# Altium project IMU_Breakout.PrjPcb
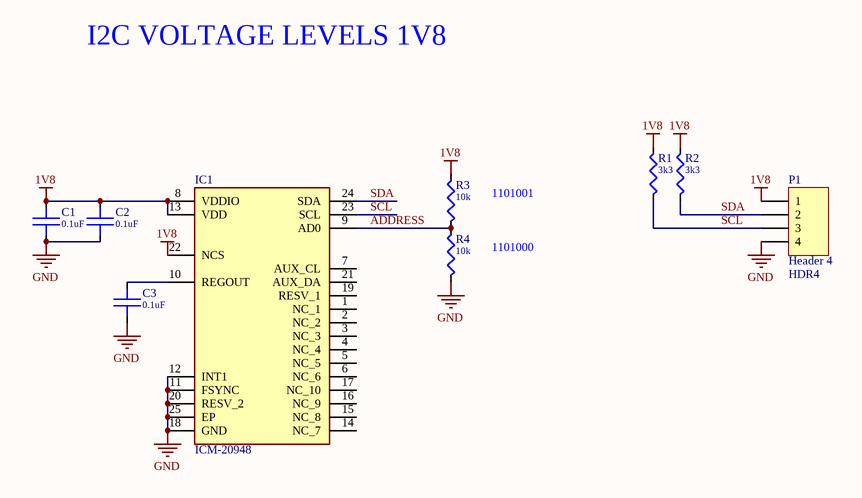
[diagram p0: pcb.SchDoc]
1 sheet, 9 parts. Net scope: global (net labels, ports and power ports of the same name join across sheets).
Board file: pcb.PcbDoc

## Sheet pcb.SchDoc
size A4; SheetNumber: 1; SheetTotal: 1

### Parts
C1  Parameter 1: 0.1uF  [CAPC1608X90N]  (hidden comment: cap0603)
C2  Parameter 1: 0.1uF  [CAPC1608X90N]  (hidden comment: cap0603)
C3  Parameter 1: 0.1uF  [CAPC1608X90N]  (hidden comment: cap0603)
IC1  ICM-20948  [QFN40P300X300X105-25N-D]
P1  Header 4  value HDR4  [HDR1X4_DIA1.5]
R1  Resistance: 3k3  [0402resistor]  (hidden comment: res0402)
R2  Resistance: 3k3  [0402resistor]  (hidden comment: res0402)
R3  Resistance: 10k  [0402resistor]  (hidden comment: res0402)
R4  Resistance: 10k  [0402resistor]  (hidden comment: res0402)

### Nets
1V8: C1.1 C2.1 IC1.8(VDDIO) IC1.13(VDD) IC1.22(NCS) P1.1 R1.1 R2.1 R3.1
GND: C1.2 C2.2 C3.2 IC1.11(FSYNC) IC1.12(INT1) IC1.18(GND) IC1.20(RESV_2) IC1.25(EP) P1.4 R4.2
ADDRESS: IC1.9(AD0) R3.2 R4.1
SCL: IC1.23(SCL) P1.3 R1.2
SDA: IC1.24(SDA) P1.2 R2.2
NetC3_1: C3.1 IC1.10(REGOUT)

Not connected (* = marked no-connect by the designer): IC1 1(NC_1) 2(NC_2) 3(NC_3) 4(NC_4) 5(NC_5) 6(NC_6) 7(AUX_CL) 14(NC_7) 15(NC_8) 16(NC_9) 17(NC_10) 19(RESV_1) 21(AUX_DA)

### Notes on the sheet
- I2C VOLTAGE LEVELS 1V8
- 1101001
- 1101000

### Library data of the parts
C1-C3 = cap0603: Capacitor; Manufacturer_Name: SAMSUNG; Manufacturer_Part_Number: CL10A106KP8NNNC
IC1 = ICM-20948: Integrated Circuit; Manufacturer_Name: TDK; Description: IMUs - Inertial Measurement Units World's Lowest Power 9-Axis MEMS MotionTracking Device
P1 = CMP-002-00093-3: Header, 4-Pin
